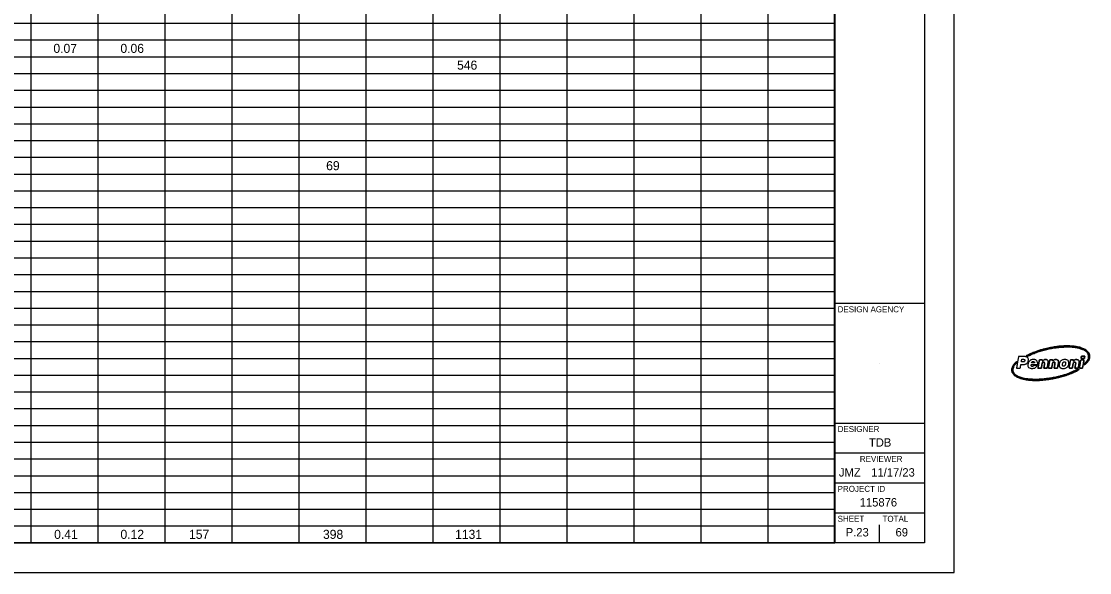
# Model space of a CAD drawing. Extents: x -0.1 to 36.1, y 0 to 22.
# Drawn here: x 18.28 to 36.14, y -0.02 to 9.19 of the extents above; entities that cross this region are included whole.
import ezdxf

# ---------------------------------------------------------------- set-up
doc = ezdxf.new("R2010")
doc.units = 0
for name, color, linetype in [('Default', 7, 'Continuous'), ('SH_Border', 7, 'Continuous'), ('SH_Cut_Line', 7, 'Continuous'), ('SH_Data', 7, 'Continuous')]:
    doc.layers.add(name, color=color, linetype=linetype)

msp = doc.modelspace()

# ---------------------------------------------------------------- linework, layer by layer
at = {"layer": 'Default'}
for p, q in [((18.439, 21.475), (18.439, 0.475)), ((19.559, 21.475), (19.559, 0.475)), ((20.679, 21.475), (20.679, 0.475)), ((21.799, 21.475), (21.799, 0.475)), ((22.919, 21.475), (22.919, 0.475)), ((24.039, 21.475), (24.039, 0.475)), ((25.159, 21.475), (25.159, 0.475)), ((26.279, 21.475), (26.279, 0.475)), ((27.399, 21.475), (27.399, 0.475)), ((28.519, 21.475), (28.519, 0.475)), ((29.639, 21.475), (29.639, 0.475)), ((30.759, 21.475), (30.759, 0.475)), ((31.879, 21.475), (31.879, 0.475)), ((1.376, 9.155), (31.879, 9.155)), ((1.376, 8.875), (31.879, 8.875)), ((1.376, 8.595), (31.879, 8.595)), ((1.376, 8.315), (31.879, 8.315)), ((1.376, 8.035), (31.879, 8.035)), ((1.376, 7.755), (31.879, 7.755)), ((1.376, 7.475), (31.879, 7.475)), ((1.376, 7.195), (31.879, 7.195)), ((1.376, 6.915), (31.879, 6.915)), ((1.376, 6.635), (31.879, 6.635)), ((1.376, 6.355), (31.879, 6.355)), ((1.376, 6.075), (31.879, 6.075)), ((1.376, 5.795), (31.879, 5.795)), ((1.376, 5.515), (31.879, 5.515)), ((1.376, 5.235), (31.879, 5.235)), ((1.376, 4.955), (31.879, 4.955)), ((1.376, 4.675), (31.879, 4.675)), ((1.376, 4.395), (31.879, 4.395)), ((1.376, 4.115), (31.879, 4.115)), ((1.376, 3.835), (31.879, 3.835)), ((1.376, 3.555), (31.879, 3.555)), ((1.376, 3.275), (31.879, 3.275)), ((1.376, 2.995), (31.879, 2.995)), ((1.376, 2.715), (31.879, 2.715)), ((1.376, 2.435), (31.879, 2.435)), ((1.376, 2.155), (31.879, 2.155)), ((1.376, 1.875), (31.879, 1.875)), ((1.376, 1.595), (31.879, 1.595)), ((1.376, 1.315), (31.879, 1.315)), ((1.376, 1.035), (31.879, 1.035)), ((1.376, 0.755), (31.879, 0.755)), ((1.376, 0.475), (31.879, 0.475))]:
    msp.add_line(p, q, dxfattribs=at)
at = {"layer": 'SH_Border'}
for p, q in [((31.876, 0.475), (31.876, 21.475)), ((31.876, 4.475), (33.376, 4.475)), ((35.217, 3.478), (35.167, 3.478)), ((31.876, 2.475), (33.376, 2.475)), ((31.876, 1.975), (33.376, 1.975)), ((31.876, 1.475), (33.376, 1.475)), ((31.876, 0.975), (33.376, 0.975))]:
    msp.add_line(p, q, dxfattribs=at)
msp.add_lwpolyline([(1.376, 21.475), (33.376, 21.475), (33.376, 0.475), (1.376, 0.475)], close=True, dxfattribs=at)
for points, degree in [([(35.076, 3.596), (35.083, 3.594), (35.089, 3.591), (35.095, 3.59), (35.097, 3.589), (35.1, 3.589), (35.102, 3.59), (35.131, 3.604), (35.159, 3.618), (35.188, 3.63), (35.229, 3.648), (35.272, 3.663), (35.315, 3.676), (35.357, 3.689), (35.399, 3.7), (35.442, 3.709), (35.482, 3.718), (35.522, 3.726), (35.562, 3.731), (35.594, 3.735), (35.626, 3.739), (35.658, 3.742), (35.684, 3.744), (35.709, 3.745), (35.734, 3.746), (35.789, 3.748), (35.844, 3.745), (35.899, 3.737), (35.928, 3.733), (35.958, 3.727), (35.986, 3.717), (36.022, 3.706), (36.055, 3.692), (36.083, 3.666), (36.098, 3.653), (36.11, 3.636), (36.115, 3.616), (36.12, 3.599), (36.122, 3.582), (36.119, 3.564), (36.115, 3.544), (36.105, 3.527), (36.093, 3.511), (36.081, 3.496), (36.067, 3.483), (36.052, 3.47), (36.051, 3.469), (36.049, 3.467), (36.048, 3.465), (36.047, 3.46), (36.046, 3.454), (36.045, 3.448), (36.045, 3.446), (36.045, 3.444), (36.044, 3.44), (36.068, 3.46), (36.091, 3.48), (36.109, 3.504), (36.118, 3.515), (36.126, 3.528), (36.131, 3.541), (36.138, 3.56), (36.138, 3.579), (36.136, 3.598), (36.132, 3.633), (36.116, 3.66), (36.09, 3.683), (36.066, 3.703), (36.039, 3.716), (36.01, 3.727), (35.972, 3.741), (35.934, 3.749), (35.895, 3.754), (35.86, 3.759), (35.825, 3.762), (35.79, 3.763), (35.733, 3.765), (35.677, 3.762), (35.621, 3.756), (35.59, 3.752), (35.559, 3.748), (35.528, 3.743), (35.483, 3.736), (35.438, 3.727), (35.394, 3.715), (35.333, 3.7), (35.274, 3.682), (35.216, 3.66), (35.175, 3.644), (35.135, 3.626), (35.096, 3.606), (35.089, 3.603), (35.083, 3.6), (35.076, 3.596)], 3), ([(35.076, 3.596), (35.083, 3.6), (35.089, 3.603), (35.096, 3.606), (35.135, 3.626), (35.175, 3.644), (35.216, 3.66), (35.274, 3.682), (35.333, 3.7), (35.394, 3.715), (35.438, 3.727), (35.483, 3.736), (35.528, 3.743), (35.559, 3.748), (35.59, 3.752), (35.621, 3.756), (35.677, 3.762), (35.733, 3.765), (35.79, 3.763), (35.825, 3.762), (35.86, 3.759), (35.895, 3.754), (35.934, 3.749), (35.972, 3.741), (36.01, 3.727), (36.039, 3.716), (36.066, 3.703), (36.09, 3.683), (36.116, 3.66), (36.132, 3.633), (36.136, 3.598), (36.138, 3.579), (36.138, 3.56), (36.131, 3.541), (36.126, 3.528), (36.118, 3.515), (36.109, 3.504), (36.091, 3.48), (36.068, 3.46), (36.044, 3.44), (36.045, 3.444), (36.045, 3.446), (36.045, 3.448), (36.046, 3.454), (36.047, 3.46), (36.048, 3.465), (36.049, 3.467), (36.051, 3.469), (36.052, 3.47), (36.067, 3.483), (36.081, 3.496), (36.093, 3.511), (36.105, 3.527), (36.115, 3.544), (36.119, 3.564), (36.122, 3.582), (36.12, 3.599), (36.115, 3.616), (36.11, 3.636), (36.098, 3.653), (36.083, 3.666), (36.055, 3.692), (36.022, 3.706), (35.986, 3.717), (35.958, 3.727), (35.928, 3.733), (35.899, 3.737), (35.844, 3.745), (35.789, 3.748), (35.734, 3.746), (35.709, 3.745), (35.684, 3.744), (35.658, 3.742), (35.626, 3.739), (35.594, 3.735), (35.562, 3.731), (35.522, 3.726), (35.482, 3.718), (35.442, 3.709), (35.399, 3.7), (35.357, 3.689), (35.315, 3.676), (35.272, 3.663), (35.229, 3.648), (35.188, 3.63), (35.159, 3.618), (35.131, 3.604), (35.102, 3.59), (35.1, 3.589), (35.097, 3.589), (35.095, 3.59), (35.089, 3.591), (35.083, 3.594), (35.076, 3.596)], 3), ([(35.088, 3.577), (35.075, 3.583), (35.062, 3.585), (35.048, 3.585), (35.016, 3.586), (34.985, 3.585), (34.953, 3.586), (34.951, 3.586), (34.95, 3.585), (34.949, 3.583), (34.946, 3.561), (34.942, 3.54), (34.938, 3.518), (34.932, 3.484), (34.926, 3.449), (34.92, 3.414), (34.919, 3.407), (34.917, 3.399), (34.916, 3.392)], 3), ([(34.989, 3.452), (34.997, 3.452), (35.004, 3.452), (35.011, 3.452), (35.024, 3.452), (35.037, 3.452), (35.05, 3.455), (35.066, 3.458), (35.081, 3.465), (35.093, 3.477), (35.108, 3.493), (35.114, 3.512), (35.114, 3.534), (35.115, 3.553), (35.106, 3.568), (35.088, 3.577)], 3), ([(36.056, 3.59), (36.054, 3.578), (36.052, 3.566), (36.05, 3.553), (36.049, 3.553), (36.048, 3.551), (36.047, 3.551), (36.029, 3.551), (36.012, 3.551), (35.994, 3.551), (35.996, 3.561), (35.997, 3.57), (35.999, 3.579), (35.999, 3.581), (36, 3.584), (36, 3.586), (36, 3.59), (36.002, 3.591), (36.005, 3.591), (36.021, 3.59), (36.036, 3.59), (36.052, 3.59), (36.053, 3.59), (36.054, 3.59), (36.056, 3.59)], 3), ([(36.056, 3.59), (36.054, 3.59), (36.053, 3.59), (36.052, 3.59), (36.036, 3.59), (36.021, 3.59), (36.005, 3.591), (36.002, 3.591), (36, 3.59), (36, 3.586), (36, 3.584), (35.999, 3.581), (35.999, 3.579), (35.997, 3.57), (35.996, 3.561), (35.994, 3.551), (36.012, 3.551), (36.029, 3.551), (36.047, 3.551), (36.048, 3.551), (36.049, 3.553), (36.05, 3.553), (36.052, 3.566), (36.054, 3.578), (36.056, 3.59)], 3), ([(35.965, 3.367), (35.964, 3.367), (35.964, 3.368), (35.964, 3.368), (35.954, 3.368), (35.944, 3.368), (35.934, 3.368), (35.932, 3.368), (35.929, 3.367), (35.927, 3.366), (35.89, 3.347), (35.852, 3.33), (35.813, 3.315), (35.755, 3.292), (35.695, 3.273), (35.635, 3.258), (35.592, 3.246), (35.549, 3.237), (35.505, 3.229), (35.48, 3.225), (35.455, 3.221), (35.431, 3.218), (35.405, 3.214), (35.379, 3.211), (35.354, 3.209), (35.33, 3.207), (35.305, 3.205), (35.281, 3.205), (35.253, 3.204), (35.225, 3.203), (35.197, 3.205), (35.166, 3.206), (35.135, 3.208), (35.104, 3.211), (35.066, 3.215), (35.028, 3.223), (34.992, 3.234), (34.96, 3.244), (34.93, 3.257), (34.903, 3.277), (34.887, 3.289), (34.873, 3.304), (34.864, 3.323), (34.851, 3.349), (34.853, 3.375), (34.863, 3.402), (34.872, 3.425), (34.886, 3.445), (34.903, 3.463), (34.908, 3.469), (34.914, 3.475), (34.914, 3.484), (34.915, 3.489), (34.916, 3.495), (34.917, 3.501), (34.916, 3.5), (34.915, 3.5), (34.914, 3.499), (34.905, 3.489), (34.895, 3.48), (34.886, 3.469), (34.867, 3.447), (34.851, 3.423), (34.842, 3.394), (34.838, 3.377), (34.836, 3.36), (34.84, 3.343), (34.844, 3.316), (34.859, 3.294), (34.879, 3.276), (34.901, 3.255), (34.928, 3.241), (34.956, 3.229), (35.003, 3.21), (35.053, 3.2), (35.103, 3.194), (35.134, 3.191), (35.165, 3.189), (35.196, 3.187), (35.238, 3.186), (35.28, 3.186), (35.323, 3.19), (35.357, 3.192), (35.391, 3.196), (35.425, 3.2), (35.456, 3.204), (35.486, 3.209), (35.517, 3.214), (35.571, 3.224), (35.625, 3.236), (35.678, 3.252), (35.723, 3.264), (35.768, 3.279), (35.812, 3.296), (35.855, 3.313), (35.897, 3.331), (35.938, 3.353), (35.947, 3.357), (35.956, 3.362), (35.965, 3.367)], 3), ([(35.965, 3.367), (35.956, 3.362), (35.947, 3.357), (35.938, 3.353), (35.897, 3.331), (35.855, 3.313), (35.812, 3.296), (35.768, 3.279), (35.723, 3.264), (35.678, 3.252), (35.625, 3.236), (35.571, 3.224), (35.517, 3.214), (35.486, 3.209), (35.456, 3.204), (35.425, 3.2), (35.391, 3.196), (35.357, 3.192), (35.323, 3.19), (35.28, 3.186), (35.238, 3.186), (35.196, 3.187), (35.165, 3.189), (35.134, 3.191), (35.103, 3.194), (35.053, 3.2), (35.003, 3.21), (34.956, 3.229), (34.928, 3.241), (34.901, 3.255), (34.879, 3.276), (34.859, 3.294), (34.844, 3.316), (34.84, 3.343), (34.836, 3.36), (34.838, 3.377), (34.842, 3.394), (34.851, 3.423), (34.867, 3.447), (34.886, 3.469), (34.895, 3.48), (34.905, 3.489), (34.914, 3.499), (34.915, 3.5), (34.916, 3.5), (34.917, 3.501), (34.916, 3.495), (34.915, 3.489), (34.914, 3.484), (34.914, 3.475), (34.908, 3.469), (34.903, 3.463), (34.886, 3.445), (34.872, 3.425), (34.863, 3.402), (34.853, 3.375), (34.851, 3.349), (34.864, 3.323), (34.873, 3.304), (34.887, 3.289), (34.903, 3.277), (34.93, 3.257), (34.96, 3.244), (34.992, 3.234), (35.028, 3.223), (35.066, 3.215), (35.104, 3.211), (35.135, 3.208), (35.166, 3.206), (35.197, 3.205), (35.225, 3.203), (35.253, 3.204), (35.281, 3.205), (35.305, 3.205), (35.33, 3.207), (35.354, 3.209), (35.379, 3.211), (35.405, 3.214), (35.431, 3.218), (35.455, 3.221), (35.48, 3.225), (35.505, 3.229), (35.549, 3.237), (35.592, 3.246), (35.635, 3.258), (35.695, 3.273), (35.755, 3.292), (35.813, 3.315), (35.852, 3.33), (35.89, 3.347), (35.927, 3.366), (35.929, 3.367), (35.932, 3.368), (35.934, 3.368), (35.944, 3.368), (35.954, 3.368), (35.964, 3.368), (35.964, 3.368), (35.964, 3.367), (35.965, 3.367)], 3), ([(34.916, 3.392), (34.917, 3.392), (34.918, 3.392), (34.918, 3.392), (34.937, 3.392), (34.957, 3.392), (34.976, 3.392), (34.979, 3.392), (34.979, 3.393), (34.979, 3.395), (34.981, 3.406), (34.983, 3.417), (34.985, 3.429), (34.987, 3.437), (34.988, 3.444), (34.989, 3.452)], 3), ([(34.997, 3.497), (35, 3.511), (35.002, 3.525), (35.005, 3.538), (35.005, 3.539), (35.006, 3.54), (35.007, 3.54), (35.018, 3.54), (35.03, 3.542), (35.041, 3.538), (35.051, 3.535), (35.055, 3.529), (35.053, 3.518)], 3), ([(35.053, 3.518), (35.051, 3.506), (35.042, 3.498), (35.029, 3.497), (35.019, 3.497), (35.008, 3.497), (34.997, 3.497)], 3), ([(35.269, 3.483), (35.265, 3.508), (35.252, 3.525), (35.228, 3.532), (35.215, 3.537), (35.202, 3.537), (35.188, 3.536), (35.166, 3.533), (35.147, 3.524), (35.131, 3.507), (35.117, 3.493), (35.11, 3.475), (35.107, 3.454), (35.104, 3.425), (35.116, 3.401), (35.146, 3.392), (35.161, 3.387), (35.178, 3.387), (35.194, 3.389), (35.212, 3.391), (35.228, 3.397), (35.242, 3.409), (35.25, 3.416), (35.256, 3.424), (35.26, 3.434)], 3), ([(35.26, 3.434), (35.243, 3.434), (35.226, 3.434), (35.21, 3.434), (35.208, 3.434), (35.207, 3.433), (35.206, 3.432), (35.202, 3.429), (35.198, 3.425), (35.194, 3.423), (35.178, 3.417), (35.16, 3.426), (35.161, 3.445), (35.161, 3.449), (35.162, 3.45), (35.166, 3.45), (35.198, 3.45), (35.231, 3.45), (35.263, 3.45), (35.264, 3.45), (35.266, 3.45), (35.268, 3.45)], 3), ([(35.167, 3.478), (35.168, 3.49), (35.178, 3.5), (35.19, 3.502), (35.196, 3.503), (35.202, 3.503), (35.207, 3.5), (35.215, 3.496), (35.219, 3.488), (35.217, 3.478)], 3), ([(35.268, 3.45), (35.27, 3.461), (35.271, 3.472), (35.269, 3.483)], 2), ([(35.275, 3.391), (35.276, 3.39), (35.276, 3.39), (35.277, 3.39), (35.294, 3.39), (35.311, 3.39), (35.328, 3.39), (35.33, 3.39), (35.331, 3.392), (35.331, 3.393), (35.332, 3.401), (35.334, 3.41), (35.335, 3.418), (35.338, 3.435), (35.341, 3.453), (35.345, 3.471), (35.347, 3.48), (35.351, 3.488), (35.361, 3.49), (35.374, 3.494), (35.388, 3.491), (35.386, 3.472), (35.384, 3.457), (35.381, 3.443), (35.379, 3.429), (35.377, 3.416), (35.374, 3.404), (35.372, 3.391), (35.373, 3.39), (35.373, 3.39), (35.374, 3.39), (35.391, 3.39), (35.408, 3.39), (35.425, 3.39), (35.428, 3.39), (35.428, 3.392), (35.428, 3.394), (35.432, 3.418), (35.437, 3.441), (35.441, 3.465), (35.443, 3.478), (35.445, 3.49), (35.444, 3.502), (35.441, 3.518), (35.432, 3.53), (35.416, 3.533), (35.395, 3.539), (35.375, 3.535), (35.358, 3.52), (35.354, 3.517), (35.351, 3.513), (35.346, 3.51), (35.348, 3.517), (35.349, 3.524), (35.35, 3.532), (35.334, 3.532), (35.318, 3.532), (35.301, 3.531), (35.301, 3.531), (35.299, 3.53), (35.299, 3.529), (35.298, 3.525), (35.297, 3.521), (35.297, 3.516), (35.291, 3.486), (35.286, 3.455), (35.281, 3.425), (35.279, 3.413), (35.277, 3.402), (35.275, 3.391)], 3), ([(35.275, 3.391), (35.277, 3.402), (35.279, 3.413), (35.281, 3.425), (35.286, 3.455), (35.291, 3.486), (35.297, 3.516), (35.297, 3.521), (35.298, 3.525), (35.299, 3.529), (35.299, 3.53), (35.301, 3.531), (35.301, 3.531), (35.318, 3.532), (35.334, 3.532), (35.35, 3.532), (35.349, 3.524), (35.348, 3.517), (35.346, 3.51), (35.351, 3.513), (35.354, 3.517), (35.358, 3.52), (35.375, 3.535), (35.395, 3.539), (35.416, 3.533), (35.432, 3.53), (35.441, 3.518), (35.444, 3.502), (35.445, 3.49), (35.443, 3.478), (35.441, 3.465), (35.437, 3.441), (35.432, 3.418), (35.428, 3.394), (35.428, 3.392), (35.428, 3.39), (35.425, 3.39), (35.408, 3.39), (35.391, 3.39), (35.374, 3.39), (35.373, 3.39), (35.373, 3.39), (35.372, 3.391), (35.374, 3.404), (35.377, 3.416), (35.379, 3.429), (35.381, 3.443), (35.384, 3.457), (35.386, 3.472), (35.388, 3.491), (35.374, 3.494), (35.361, 3.49), (35.351, 3.488), (35.347, 3.48), (35.345, 3.471), (35.341, 3.453), (35.338, 3.435), (35.335, 3.418), (35.334, 3.41), (35.332, 3.401), (35.331, 3.393), (35.331, 3.392), (35.33, 3.39), (35.328, 3.39), (35.311, 3.39), (35.294, 3.39), (35.277, 3.39), (35.276, 3.39), (35.276, 3.39), (35.275, 3.391)], 3), ([(35.448, 3.391), (35.448, 3.39), (35.449, 3.39), (35.449, 3.39), (35.466, 3.39), (35.484, 3.39), (35.501, 3.39), (35.502, 3.39), (35.504, 3.392), (35.504, 3.393), (35.507, 3.41), (35.51, 3.427), (35.513, 3.444), (35.515, 3.454), (35.516, 3.465), (35.519, 3.475), (35.523, 3.488), (35.535, 3.494), (35.548, 3.491), (35.554, 3.49), (35.558, 3.486), (35.559, 3.48), (35.559, 3.477), (35.559, 3.474), (35.559, 3.471), (35.557, 3.46), (35.555, 3.448), (35.553, 3.437), (35.551, 3.422), (35.548, 3.406), (35.545, 3.391), (35.546, 3.391), (35.546, 3.39), (35.546, 3.39), (35.563, 3.39), (35.581, 3.39), (35.599, 3.39), (35.599, 3.39), (35.601, 3.392), (35.601, 3.393), (35.605, 3.416), (35.609, 3.438), (35.613, 3.46), (35.615, 3.472), (35.617, 3.484), (35.617, 3.497), (35.617, 3.512), (35.611, 3.525), (35.595, 3.531), (35.575, 3.539), (35.555, 3.537), (35.537, 3.525), (35.531, 3.52), (35.526, 3.515), (35.52, 3.51), (35.521, 3.518), (35.522, 3.524), (35.523, 3.532), (35.507, 3.532), (35.491, 3.532), (35.475, 3.532), (35.472, 3.532), (35.472, 3.53), (35.472, 3.528), (35.468, 3.504), (35.464, 3.48), (35.459, 3.457), (35.456, 3.435), (35.452, 3.413), (35.448, 3.391)], 3), ([(35.448, 3.391), (35.452, 3.413), (35.456, 3.435), (35.459, 3.457), (35.464, 3.48), (35.468, 3.504), (35.472, 3.528), (35.472, 3.53), (35.472, 3.532), (35.475, 3.532), (35.491, 3.532), (35.507, 3.532), (35.523, 3.532), (35.522, 3.524), (35.521, 3.518), (35.52, 3.51), (35.526, 3.515), (35.531, 3.52), (35.537, 3.525), (35.555, 3.537), (35.575, 3.539), (35.595, 3.531), (35.611, 3.525), (35.617, 3.512), (35.617, 3.497), (35.617, 3.484), (35.615, 3.472), (35.613, 3.46), (35.609, 3.438), (35.605, 3.416), (35.601, 3.393), (35.601, 3.392), (35.599, 3.39), (35.599, 3.39), (35.581, 3.39), (35.563, 3.39), (35.546, 3.39), (35.546, 3.39), (35.546, 3.391), (35.545, 3.391), (35.548, 3.406), (35.551, 3.422), (35.553, 3.437), (35.555, 3.448), (35.557, 3.46), (35.559, 3.471), (35.559, 3.474), (35.559, 3.477), (35.559, 3.48), (35.558, 3.486), (35.554, 3.49), (35.548, 3.491), (35.535, 3.494), (35.523, 3.488), (35.519, 3.475), (35.516, 3.465), (35.515, 3.454), (35.513, 3.444), (35.51, 3.427), (35.507, 3.41), (35.504, 3.393), (35.504, 3.392), (35.502, 3.39), (35.501, 3.39), (35.484, 3.39), (35.466, 3.39), (35.449, 3.39), (35.449, 3.39), (35.448, 3.39), (35.448, 3.391)], 3), ([(35.791, 3.483), (35.79, 3.505), (35.778, 3.521), (35.758, 3.529), (35.739, 3.537), (35.719, 3.537), (35.699, 3.533), (35.675, 3.528), (35.656, 3.516), (35.643, 3.495), (35.641, 3.493), (35.64, 3.49), (35.639, 3.488), (35.638, 3.486), (35.637, 3.484), (35.636, 3.482), (35.631, 3.471), (35.628, 3.459), (35.628, 3.447), (35.628, 3.445), (35.628, 3.442), (35.628, 3.44), (35.628, 3.432), (35.63, 3.425), (35.633, 3.419), (35.633, 3.418), (35.634, 3.416), (35.634, 3.415), (35.635, 3.414), (35.636, 3.413), (35.636, 3.412), (35.639, 3.409), (35.642, 3.405), (35.645, 3.402), (35.647, 3.401), (35.649, 3.399), (35.651, 3.398), (35.652, 3.397), (35.652, 3.397), (35.653, 3.397), (35.654, 3.396), (35.655, 3.395), (35.656, 3.395), (35.658, 3.394), (35.66, 3.393), (35.662, 3.392), (35.673, 3.388), (35.685, 3.386), (35.697, 3.386)], 3), ([(35.684, 3.446), (35.685, 3.463), (35.687, 3.476), (35.696, 3.488), (35.701, 3.494), (35.708, 3.498), (35.716, 3.498), (35.725, 3.498), (35.731, 3.495), (35.733, 3.486), (35.735, 3.48), (35.735, 3.473), (35.735, 3.466)], 3), ([(35.735, 3.466), (35.734, 3.456), (35.731, 3.446), (35.726, 3.437), (35.72, 3.427), (35.71, 3.422), (35.7, 3.424), (35.693, 3.425), (35.689, 3.428), (35.686, 3.435), (35.685, 3.439), (35.684, 3.444), (35.684, 3.446)], 3), ([(35.697, 3.386), (35.704, 3.386), (35.711, 3.387), (35.718, 3.388), (35.737, 3.392), (35.754, 3.4), (35.767, 3.414), (35.785, 3.434), (35.792, 3.457), (35.791, 3.483)], 3), ([(35.819, 3.531), (35.81, 3.484), (35.802, 3.438), (35.794, 3.39), (35.813, 3.39), (35.831, 3.39), (35.849, 3.39), (35.852, 3.405), (35.854, 3.419), (35.857, 3.433), (35.859, 3.446), (35.861, 3.459), (35.864, 3.471), (35.867, 3.485), (35.877, 3.492), (35.891, 3.492), (35.899, 3.491), (35.904, 3.487), (35.905, 3.478), (35.905, 3.475), (35.905, 3.472), (35.905, 3.469), (35.902, 3.45), (35.898, 3.431), (35.895, 3.412), (35.894, 3.405), (35.893, 3.398), (35.891, 3.39), (35.91, 3.39), (35.928, 3.39), (35.947, 3.39), (35.947, 3.392), (35.947, 3.393), (35.948, 3.394), (35.951, 3.415), (35.955, 3.437), (35.959, 3.458), (35.961, 3.472), (35.964, 3.485), (35.963, 3.5), (35.962, 3.516), (35.953, 3.528), (35.937, 3.533), (35.912, 3.54), (35.891, 3.534), (35.872, 3.516), (35.87, 3.514), (35.868, 3.512), (35.866, 3.51), (35.866, 3.51), (35.866, 3.51), (35.866, 3.511), (35.867, 3.517), (35.868, 3.524), (35.869, 3.531), (35.852, 3.531), (35.836, 3.531), (35.819, 3.531)], 3), ([(35.819, 3.531), (35.836, 3.531), (35.852, 3.531), (35.869, 3.531), (35.868, 3.524), (35.867, 3.517), (35.866, 3.511), (35.866, 3.51), (35.866, 3.51), (35.866, 3.51), (35.868, 3.512), (35.87, 3.514), (35.872, 3.516), (35.891, 3.534), (35.912, 3.54), (35.937, 3.533), (35.953, 3.528), (35.962, 3.516), (35.963, 3.5), (35.964, 3.485), (35.961, 3.472), (35.959, 3.458), (35.955, 3.437), (35.951, 3.415), (35.948, 3.394), (35.947, 3.393), (35.947, 3.392), (35.947, 3.39), (35.928, 3.39), (35.91, 3.39), (35.891, 3.39), (35.893, 3.398), (35.894, 3.405), (35.895, 3.412), (35.898, 3.431), (35.902, 3.45), (35.905, 3.469), (35.905, 3.472), (35.905, 3.475), (35.905, 3.478), (35.904, 3.487), (35.899, 3.491), (35.891, 3.492), (35.877, 3.492), (35.867, 3.485), (35.864, 3.471), (35.861, 3.459), (35.859, 3.446), (35.857, 3.433), (35.854, 3.419), (35.852, 3.405), (35.849, 3.39), (35.831, 3.39), (35.813, 3.39), (35.794, 3.39), (35.802, 3.438), (35.81, 3.484), (35.819, 3.531)], 3), ([(36.021, 3.392), (36.003, 3.392), (35.985, 3.392), (35.966, 3.392), (35.974, 3.439), (35.982, 3.485), (35.991, 3.532), (36.009, 3.532), (36.027, 3.532), (36.046, 3.532), (36.038, 3.485), (36.03, 3.439), (36.021, 3.392)], 3), ([(36.021, 3.392), (36.03, 3.439), (36.038, 3.485), (36.046, 3.532), (36.027, 3.532), (36.009, 3.532), (35.991, 3.532), (35.982, 3.485), (35.974, 3.439), (35.966, 3.392), (35.985, 3.392), (36.003, 3.392), (36.021, 3.392)], 3)]:
    msp.add_open_spline(points, degree=degree, dxfattribs=at)
at = {"layer": 'SH_Cut_Line'}
msp.add_lwpolyline([(-0.124, -0.025), (33.876, -0.025), (33.876, 21.975), (-0.124, 21.975)], close=True, dxfattribs=at)
at = {"layer": 'SH_Data'}
for p, q in [((32.626, 3.475), (32.626, 3.475)), ((32.626, 0.475), (32.626, 0.775)), ((32.251, 0.65), (32.251, 0.65))]:
    msp.add_line(p, q, dxfattribs=at)

# ---------------------------------------------------------------- texts
at = {"layer": 'Default'}
for s, p in [('0.07', (18.818, 8.659)), ('0.06', (19.938, 8.659)), ('546', (25.565, 8.379)), ('69', (23.377, 6.699)), ('0.41', (18.831, 0.539)), ('0.12', (19.939, 0.539)), ('157', (21.085, 0.539)), ('398', (23.324, 0.539)), ('1131', (25.532, 0.539))]:
    msp.add_text(s, height=0.1515, dxfattribs=at).set_placement(p)
at = {"layer": 'SH_Data'}
for s, height, p in [('DESIGN AGENCY', 0.1, (31.926, 4.325)), ('DESIGNER', 0.1, (31.926, 2.325)), ('TDB', 0.14, (32.449, 2.08)), ('REVIEWER', 0.1, (32.297, 1.825)), ('JMZ', 0.14, (31.947, 1.58)), ('11/17/23', 0.14, (32.487, 1.58)), ('PROJECT ID', 0.1, (31.926, 1.325)), ('115876', 0.14, (32.295, 1.08)), ('SHEET', 0.1, (31.926, 0.825)), ('TOTAL', 0.1, (32.676, 0.825)), ('P.23', 0.14, (32.061, 0.58)), ('69', 0.14, (32.894, 0.58))]:
    msp.add_text(s, height=height, dxfattribs=at).set_placement(p)

doc.saveas('drawing.dxf')
